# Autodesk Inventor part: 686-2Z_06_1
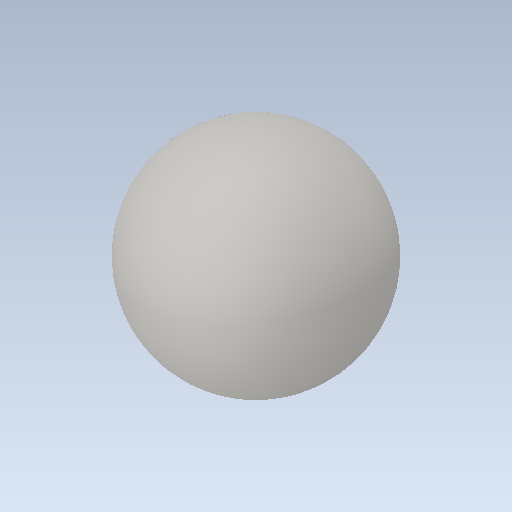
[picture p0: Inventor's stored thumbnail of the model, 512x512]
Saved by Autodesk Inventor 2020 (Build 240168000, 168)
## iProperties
Created: 2017-11
Part Number: 686-2Z_06_1
Material: Ogólny
Document SubType Name: Modeling
Designer: Tomasz
Density: 1 g/cm^3
Appearance: Domyślna
Sending System: SolidWorks 2017
Last Author: Tomasz
Last Saved: 2017-11-19
Source: 686-2Z_06_1
Author: Tomasz
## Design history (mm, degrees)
feature "Imported1"
node "Bryła1"
